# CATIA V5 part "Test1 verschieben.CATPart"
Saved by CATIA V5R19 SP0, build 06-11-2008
Part number: Test1 verschieben
Bounding box of the stored display mesh (mm): x 0 to 50, y 0 to 25, z 0 to 50
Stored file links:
  P:\Catia\Test\Test1 verschieben.CATPart
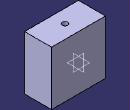
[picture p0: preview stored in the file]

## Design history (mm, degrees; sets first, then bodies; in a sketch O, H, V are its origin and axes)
Body1 (main body)
  Sketch1 on xy-plane, origin (0, 0, 0), H (1, 0, 0), V (0, 1, 0)
    point P1 (0, 25)
    line L1 (0, 25) -> (50, 25)
    line L2 (50, 25) -> (50, 0)
    line L3 (50, 0) -> (0, 0)
    line L4 (0, 0) -> (0, 25)
    point P3 (50, 0)
    length L1 = 50
    length L2 = 25
    coincidence: P1 V, P3 H
    horizontal: L1 H, L3 H
    vertical: L2 V, L4 V
  Pad1: profile Sketch1, direction (0, 0, 1), length 50
  Sketch2 on end face of Pad1, origin (14.9614, 13.1233, 50), H (1, 0, 0), V (0, 1, 0)
    point P1 (10.0386, -0.6233)
    reference projected point E1 (10.0386, -0.6233) from vertex of DatumPoint1
    coincidence: E1 P1
  Hole1: placed by Sketch2, at (25, 12.5, 50) direction (0, 0, -1), diameter 4.917, depth 25, threaded, thread diameter 6, thread depth 15, pitch 1
  DatumPoint1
